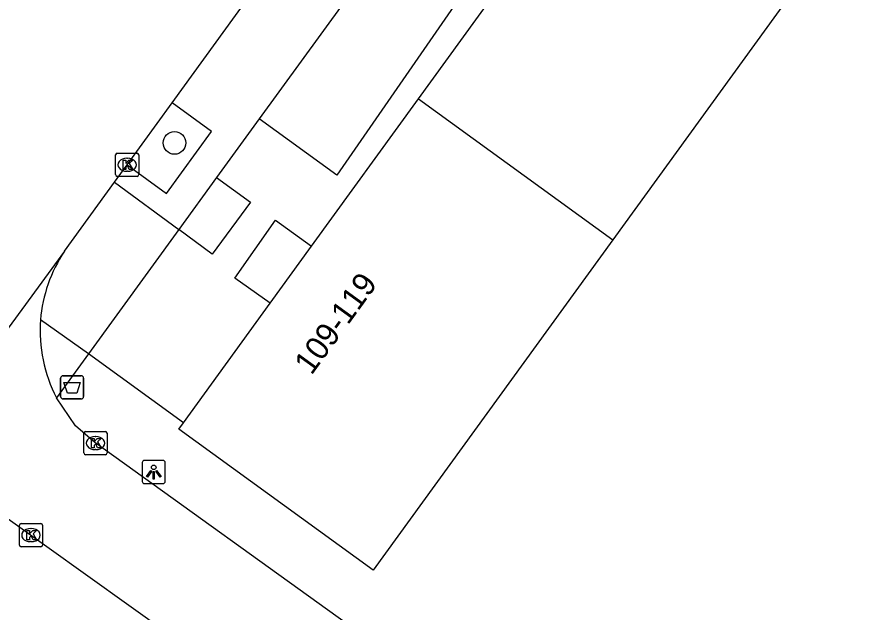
# Model space of a CAD drawing. Extents: x 159675 to 160530, y 382179 to 382901.
# Drawn here: x 160242.45 to 160278.5, y 382512.84 to 382538.52 of the extents above; entities that cross this region are included whole.
import ezdxf

# ---------------------------------------------------------------- set-up
doc = ezdxf.new("R2010")
doc.units = 0
for name, color, linetype in [('IMGEO_Afvalbak', 7, 'Continuous'), ('IMGEO_Boom', 7, 'Continuous'), ('IMGEO_Kolk', 7, 'Continuous'), ('IMGEO_Lichtpunt', 7, 'Continuous'), ('IMGEO_Pand', 7, 'Continuous'), ('IMGEO_Pand_nummerreeks', 7, 'Continuous'), ('IMGEO_Rijbaan_lokaal_gesloten', 7, 'Continuous'), ('IMGEO_Rijbaan_lokaal_open', 7, 'Continuous'), ('IMGEO_Voetpad_open', 7, 'Continuous')]:
    doc.layers.add(name, color=color, linetype=linetype)

msp = doc.modelspace()

# ---------------------------------------------------------------- linework, layer by layer
at = {"layer": 'IMGEO_Afvalbak'}
for p, q in [((160244.35, 382522.138), (160244.35, 382522.938)), ((160244.35, 382522.938), (160244.35, 382522.138)), ((160244.45, 382523.038), (160245.24, 382523.038)), ((160245.24, 382523.038), (160244.45, 382523.038)), ((160245.34, 382522.938), (160245.34, 382522.138)), ((160245.34, 382522.138), (160245.34, 382522.938)), ((160245.24, 382522.038), (160244.45, 382522.038)), ((160244.45, 382522.038), (160245.24, 382522.038))]:
    msp.add_line(p, q, dxfattribs=at)
msp.add_lwpolyline([(160244.493, 382522.752), (160245.197, 382522.752), (160245.048, 382522.282), (160244.642, 382522.282), (160244.493, 382522.752)], dxfattribs=at)
for centre, start, end in [((160244.45, 382522.938), 90, 180), ((160244.45, 382522.938), 90, 180), ((160245.24, 382522.938), 0, 90), ((160245.24, 382522.938), 360, 90), ((160244.45, 382522.138), 180, 270), ((160244.45, 382522.138), 180, 270), ((160245.24, 382522.138), 270, 0), ((160245.24, 382522.138), 270, 0)]:
    msp.add_arc(centre, 0.1, start, end, dxfattribs=at)
at = {"layer": 'IMGEO_Boom'}
msp.add_circle((160249.261, 382533.079), 0.489, dxfattribs=at)
at = {"layer": 'IMGEO_Kolk'}
for p, q in [((160246.718, 382531.71), (160246.718, 382532.562)), ((160246.793, 382532.636), (160247.645, 382532.636)), ((160247.206, 382532.416), (160247.231, 382532.416)), ((160247.719, 382532.562), (160247.719, 382531.71)), ((160247.229, 382531.856), (160247.204, 382531.856)), ((160247.645, 382531.636), (160246.793, 382531.636)), ((160245.352, 382519.706), (160245.352, 382520.558)), ((160245.427, 382520.632), (160246.279, 382520.632)), ((160246.353, 382520.558), (160246.353, 382519.706)), ((160245.84, 382520.412), (160245.865, 382520.412)), ((160245.863, 382519.852), (160245.838, 382519.852)), ((160246.279, 382519.632), (160245.427, 382519.632)), ((160242.569, 382515.737), (160242.569, 382516.589)), ((160242.644, 382516.663), (160243.496, 382516.663)), ((160243.57, 382516.589), (160243.57, 382515.737)), ((160243.057, 382516.443), (160243.082, 382516.443)), ((160243.08, 382515.883), (160243.055, 382515.883)), ((160243.496, 382515.663), (160242.644, 382515.663))]:
    msp.add_line(p, q, dxfattribs=at)
for points in [[(160246.718, 382531.71), (160246.718, 382532.562)], [(160246.793, 382532.636), (160247.645, 382532.636)], [(160247.719, 382532.562), (160247.719, 382531.71)], [(160247.039, 382532.336), (160247.162, 382532.336), (160247.162, 382532.185), (160247.292, 382532.336), (160247.456, 382532.336), (160247.31, 382532.185), (160247.463, 382531.936), (160247.311, 382531.936), (160247.226, 382532.1), (160247.162, 382532.033), (160247.162, 382531.936), (160247.039, 382531.936), (160247.039, 382532.336)], [(160247.645, 382531.636), (160246.793, 382531.636)], [(160245.352, 382519.706), (160245.352, 382520.558)], [(160245.427, 382520.632), (160246.279, 382520.632)], [(160246.353, 382520.558), (160246.353, 382519.706)], [(160245.673, 382520.332), (160245.796, 382520.332), (160245.796, 382520.181), (160245.926, 382520.332), (160246.09, 382520.332), (160245.944, 382520.181), (160246.097, 382519.932), (160245.945, 382519.932), (160245.86, 382520.096), (160245.796, 382520.029), (160245.796, 382519.932), (160245.673, 382519.932), (160245.673, 382520.332)], [(160246.279, 382519.632), (160245.427, 382519.632)], [(160242.569, 382515.737), (160242.569, 382516.589)], [(160242.644, 382516.663), (160243.496, 382516.663)], [(160243.57, 382516.589), (160243.57, 382515.737)], [(160242.89, 382516.363), (160243.013, 382516.363), (160243.013, 382516.212), (160243.143, 382516.363), (160243.307, 382516.363), (160243.161, 382516.212), (160243.314, 382515.963), (160243.162, 382515.963), (160243.077, 382516.127), (160243.013, 382516.06), (160243.013, 382515.963), (160242.89, 382515.963), (160242.89, 382516.363)], [(160243.496, 382515.663), (160242.644, 382515.663)]]:
    msp.add_lwpolyline(points, dxfattribs=at)
for centre, start, end in [((160246.795, 382532.56), 91.552, 178.448), ((160246.795, 382532.56), 91.552, 178.448), ((160247.643, 382532.56), 1.552, 88.448), ((160247.643, 382532.56), 1.552, 88.448), ((160246.795, 382531.712), 181.552, 268.448), ((160246.795, 382531.712), 181.552, 268.448), ((160247.643, 382531.712), 271.552, 358.448), ((160247.643, 382531.712), 271.552, 358.448), ((160245.429, 382520.556), 91.552, 178.448), ((160245.429, 382520.556), 91.552, 178.448), ((160246.277, 382520.556), 1.552, 88.448), ((160246.277, 382520.556), 1.552, 88.448), ((160245.429, 382519.708), 181.552, 268.448), ((160245.429, 382519.708), 181.552, 268.448), ((160246.277, 382519.708), 271.552, 358.448), ((160246.277, 382519.708), 271.552, 358.448), ((160242.646, 382516.587), 91.552, 178.448), ((160242.646, 382516.587), 91.552, 178.448), ((160243.494, 382516.587), 1.552, 88.448), ((160243.494, 382516.587), 1.552, 88.448), ((160242.646, 382515.739), 181.552, 268.448), ((160242.646, 382515.739), 181.552, 268.448), ((160243.494, 382515.739), 271.552, 358.448), ((160243.494, 382515.739), 271.552, 358.448)]:
    msp.add_arc(centre, 0.0765, start, end, dxfattribs=at)
for centre, major_axis, ratio, start_param, end_param in [((160247.205, 382532.136), (-0.387, 0.002), 0.722429, 4.712389, 7.853982), ((160247.23, 382532.136), (-0.39, 0.002), 0.717154, 1.570796, 4.712389), ((160245.839, 382520.132), (-0.387, 0.002), 0.722429, 4.712389, 7.853982), ((160245.864, 382520.132), (-0.39, 0.002), 0.717154, 1.570796, 4.712389), ((160243.056, 382516.163), (-0.387, 0.002), 0.722429, 4.712389, 7.853982), ((160243.081, 382516.163), (-0.39, 0.002), 0.717154, 1.570796, 4.712389)]:
    msp.add_ellipse(centre, major_axis=major_axis, ratio=ratio, start_param=start_param, end_param=end_param, dxfattribs=at)
at = {"layer": 'IMGEO_Lichtpunt'}
for p, q in [((160247.867, 382519.289), (160247.867, 382518.482)), ((160247.867, 382519.289), (160247.867, 382518.482)), ((160248.769, 382519.384), (160247.961, 382519.384)), ((160248.769, 382519.384), (160247.961, 382519.384)), ((160248.863, 382518.482), (160248.863, 382519.289)), ((160248.863, 382518.482), (160248.863, 382519.289)), ((160247.961, 382518.388), (160248.769, 382518.388)), ((160247.961, 382518.388), (160248.769, 382518.388))]:
    msp.add_line(p, q, dxfattribs=at)
for points in [[(160248.241, 382518.953), (160248.28, 382518.925), (160248.092, 382518.663), (160248.054, 382518.69), (160248.241, 382518.953)], [(160248.343, 382518.905), (160248.39, 382518.905), (160248.39, 382518.583), (160248.343, 382518.583), (160248.343, 382518.905)], [(160248.453, 382518.925), (160248.491, 382518.952), (160248.678, 382518.69), (160248.639, 382518.662), (160248.453, 382518.925)]]:
    msp.add_lwpolyline(points, dxfattribs=at)
msp.add_circle((160248.366, 382519.087), 0.0994, dxfattribs=at)
for centre, start, end in [((160247.961, 382519.289), 90, 180), ((160247.961, 382519.289), 90, 180), ((160248.769, 382519.289), 0, 90), ((160248.769, 382519.289), 0, 90), ((160247.961, 382518.482), 180, 270), ((160247.961, 382518.482), 180, 270), ((160248.769, 382518.482), 270, 0), ((160248.769, 382518.482), 270, 360)]:
    msp.add_arc(centre, 0.0946, start, end, dxfattribs=at)
at = {"layer": 'IMGEO_Pand'}
for points in [[(160278.496, 382543.145), (160268.164, 382528.897)], [(160259.779, 382534.976), (160264.849, 382541.967)], [(160255.17, 382528.62), (160259.779, 382534.976)], [(160259.779, 382534.976), (160268.164, 382528.897)], [(160268.164, 382528.897), (160257.833, 382514.648), (160249.448, 382520.727), (160249.654, 382521.011)], [(160253.392, 382526.166), (160255.17, 382528.62)], [(160249.654, 382521.011), (160253.392, 382526.166)]]:
    msp.add_lwpolyline(points, dxfattribs=at)
at = {"layer": 'IMGEO_Rijbaan_lokaal_gesloten'}
for points in [[(160249.155, 382534.809), (160256.944, 382545.554)], [(160247.218, 382532.137), (160249.155, 382534.809)], [(160246.675, 382531.388), (160247.218, 382532.137)], [(160244.516, 382528.409), (160246.675, 382531.388)], [(160244.516, 382528.409), (160235.142, 382515.615)]]:
    msp.add_lwpolyline(points, dxfattribs=at)
at = {"layer": 'IMGEO_Rijbaan_lokaal_open'}
for points in [[(160268.454, 382503.881), (160245.826, 382520.154), (160244.991, 382520.879), (160244.168, 382522.085)], [(160241.981, 382516.945), (160263.203, 382501.762)]]:
    msp.add_lwpolyline(points, dxfattribs=at)
for centre, radius, start, end in [((160249.642, 382524.958), 6.18, 146.0514, 175.4616), ((160249.67, 382524.959), 6.207, 175.4871, 207.5781)]:
    msp.add_arc(centre, radius, start, end, dxfattribs=at)
at = {"layer": 'IMGEO_Voetpad_open'}
for points in [[(160258.34, 382541.598), (160261.573, 382539.364), (160256.263, 382531.683), (160252.908, 382534.119)], [(160258.34, 382541.598), (160252.908, 382534.119)], [(160247.218, 382532.137), (160248.919, 382530.904), (160250.856, 382533.576), (160249.155, 382534.809)], [(160252.908, 382534.119), (160251.073, 382531.592)], [(160246.675, 382531.388), (160249.443, 382529.348)], [(160251.073, 382531.592), (160252.536, 382530.53), (160250.883, 382528.287), (160249.443, 382529.348)], [(160251.073, 382531.592), (160249.443, 382529.348)], [(160253.392, 382526.166), (160251.861, 382527.246), (160253.623, 382529.742), (160255.17, 382528.62)], [(160249.443, 382529.348), (160245.549, 382523.987)], [(160245.549, 382523.987), (160243.482, 382525.447)], [(160245.549, 382523.987), (160244.168, 382522.085)], [(160249.654, 382521.011), (160245.549, 382523.987)]]:
    msp.add_lwpolyline(points, dxfattribs=at)

# ---------------------------------------------------------------- texts
at = {"layer": 'IMGEO_Pand_nummerreeks'}
msp.add_text('109-119', height=1, rotation=54.0528, dxfattribs=at).set_placement((160255.168, 382523.029))

doc.saveas('drawing.dxf')
